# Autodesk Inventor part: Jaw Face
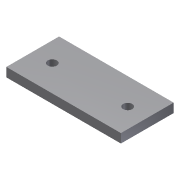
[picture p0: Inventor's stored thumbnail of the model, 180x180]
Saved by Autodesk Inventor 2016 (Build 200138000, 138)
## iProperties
Shininess: 77.0
Length Units: 11269
Angle Units: 11279
Time Units: 11290
Mass Units: 11283
Length Display Precision: 3
Angle Display Precision: 2
Compacted: True
Created: 2002-02
Part Number: Jaw Face
Document SubType Name: Modeling
Designer: ***
Density: 1 g/cm^3
Material: Generic
Mass: 15.6207 g
Surface Area: 67.651 cm^2
Volume: 15.6207 cm^3
Appearance: Default
Density: 0.0
Volumn: 0.0
Area: 0.0
PropertySet Name: Model Information
Control State: 0
Master: False
Checked Out: False
Author: ***
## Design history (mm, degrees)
sketch "Sketch1"
  geometry: L1 (-79.661, -8.43)-(-3.661, -8.43); L2 (-3.661, -8.43)-(-3.661, -43.43); L3 (-3.661, -43.43)-(-79.661, -43.43); L4 (-79.661, -43.43)-(-79.661, -8.43); C1 r 3 at (-66.661, -25.93); C2 r 3 at (-16.661, -25.93)
  constraints: 8 end point, 2 centre point, 2 parallel, 1 equal radius, 1 horizontal, 1 perpendicular
  dimensions: "d0" = 76 distance of L2.end L3.end; "d1" = 6 diameter of C1; "d2" = 50 distance of C2.centre C1.centre; "d3" = 35 distance of L1.end L2.end; "d4" = 17.5 distance from line of L3 C2.centre; "d5" = 13 distance from line of L2 C2.centre; "d6" = 13 distance from line of L4 C1.centre
extrude "Extrusion1" new body sketch "Sketch1" stored distance "d7" = 6; taper "d8" = 0 deg
body "Solid1"
